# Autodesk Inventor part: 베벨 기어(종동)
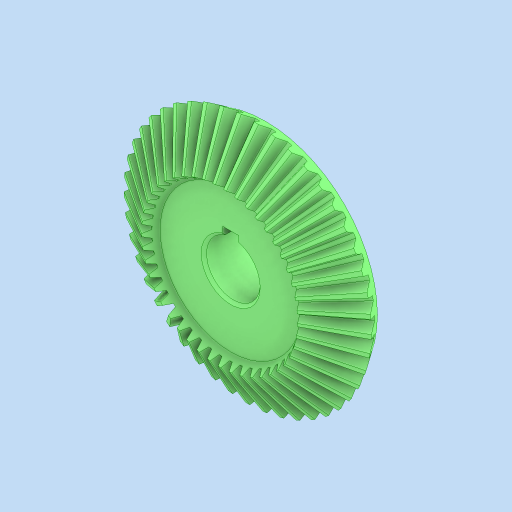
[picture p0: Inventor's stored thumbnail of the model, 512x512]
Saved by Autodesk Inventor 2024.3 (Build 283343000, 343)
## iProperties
Created: 2026-01
Part Number: 베벨 기어(종동)
Material: 강철, 합금
Document SubType Name: Modeling
Designer: PC2-02
Density: 7.73 g/cm^3
Appearance: 기본값
Author: jhkim
Sending System: Autodesk Inventor 2026
Preprocessor: ST-DEVELOPER v20.1
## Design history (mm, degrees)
node "베벨 기어(종동)1"
node "솔리드1"
body "Solid1"
